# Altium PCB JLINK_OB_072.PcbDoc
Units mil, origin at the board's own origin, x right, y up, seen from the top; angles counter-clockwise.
Board outline 1377.95 x 708.66 mil, 2 copper layers (Top Layer, Bottom Layer); 27 components, 25 nets, 147 pads, 33 vias.
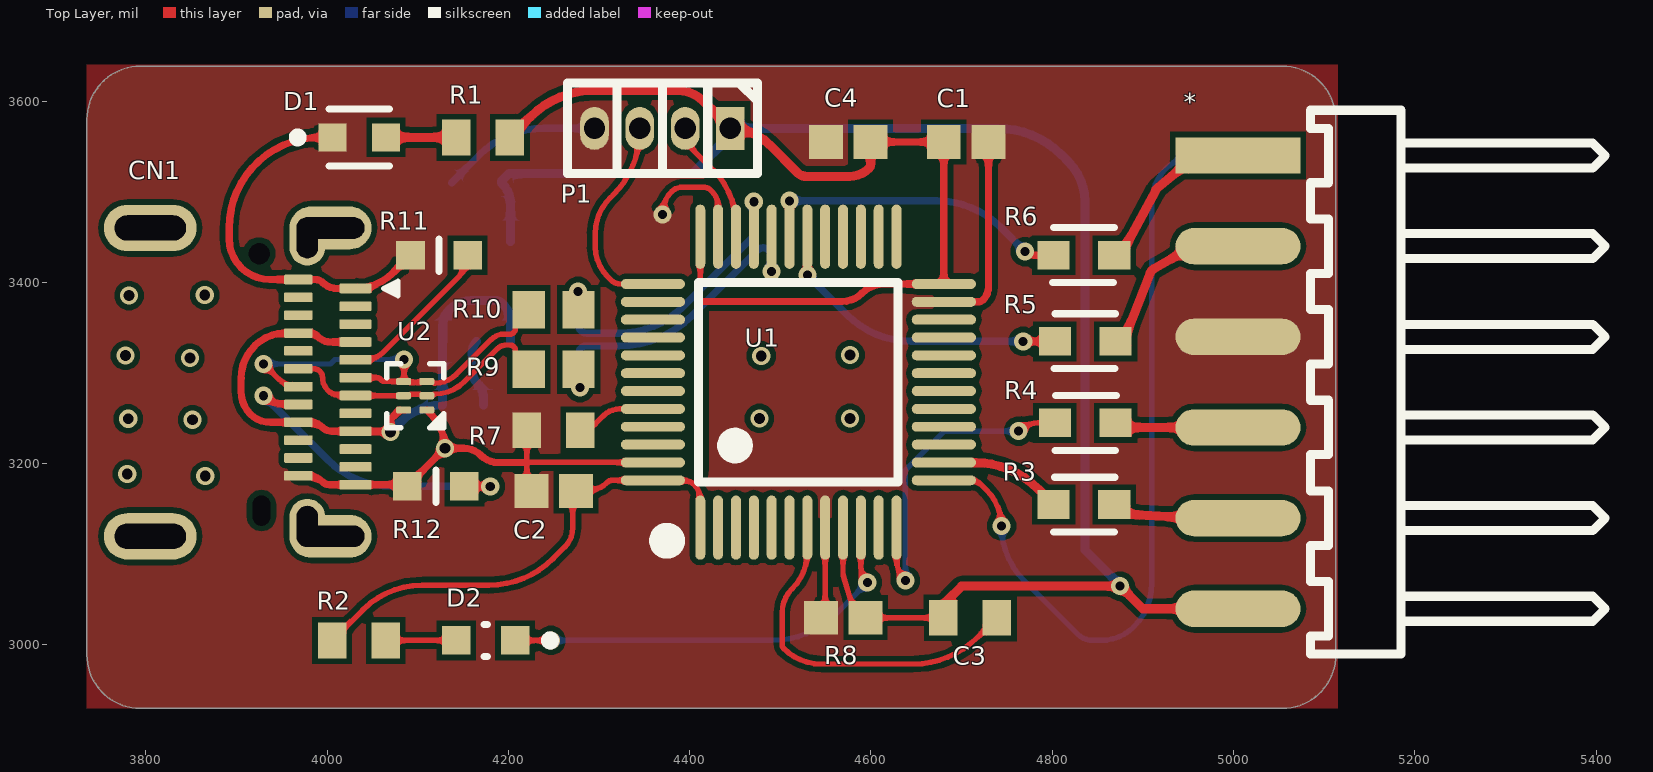
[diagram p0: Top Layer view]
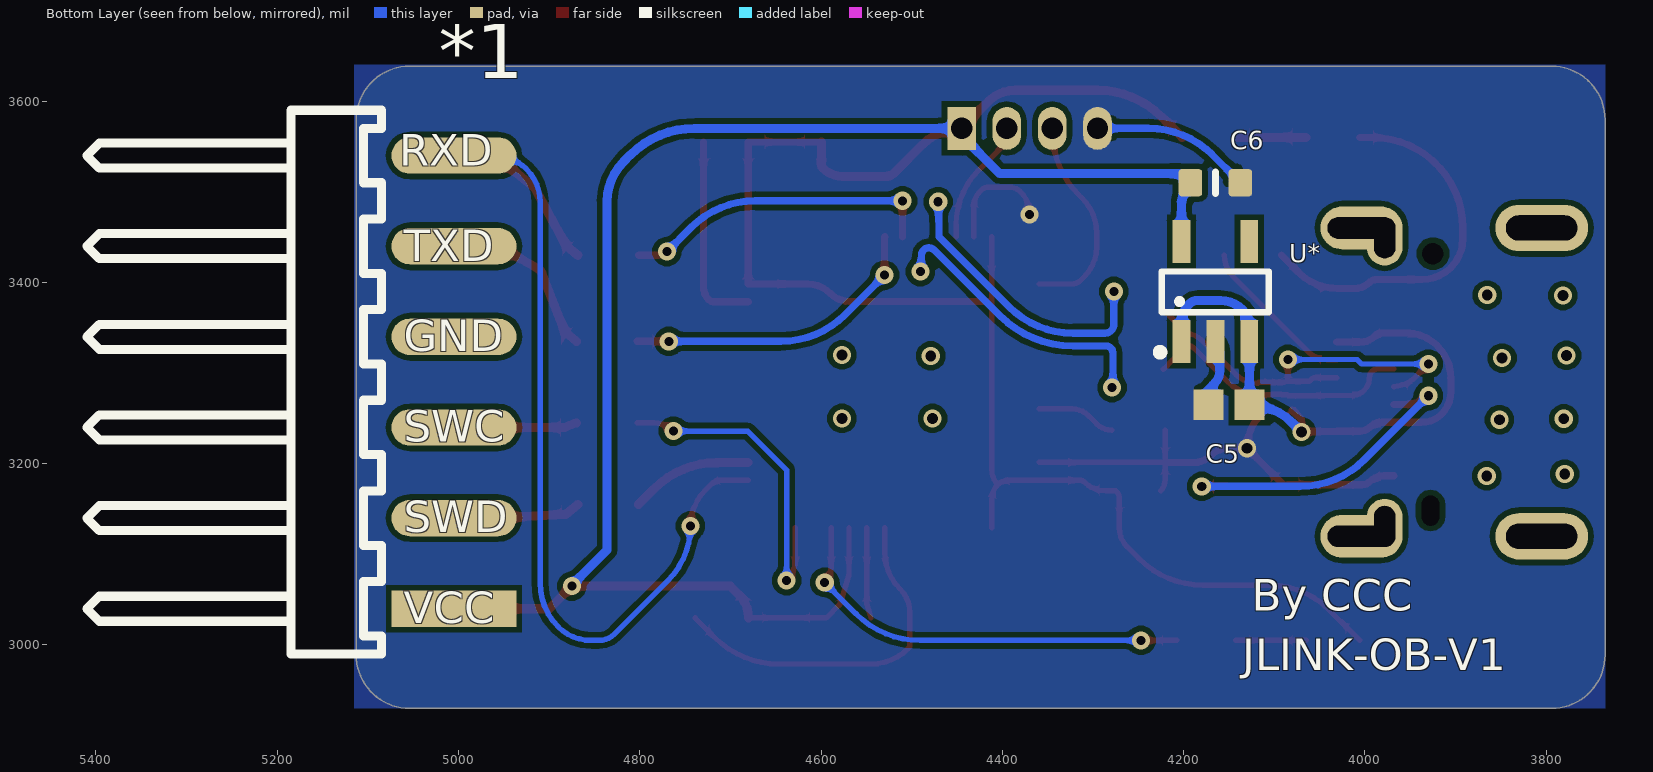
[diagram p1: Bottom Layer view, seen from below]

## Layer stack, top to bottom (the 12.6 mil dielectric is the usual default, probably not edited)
Top Solder: solder mask 0.4, Solder Resist, Dk 3.5
Top Layer: signal copper 1.4
Dielectric 1: dielectric 12.6, FR-4, Dk 4.8
Bottom Layer: signal copper 1.4
Bottom Solder: solder mask 0.4, Solder Resist, Dk 3.5

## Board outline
3735,2989.06 3735,3579.61 cw(c3794.06,3579.61) 3794.06,3638.66 5053.9,3638.66 cw(c5053.9,3579.61) 5112.95,3579.61 5112.95,2989.06 cw(c5053.9,2989.06) 5053.9,2930 3794.06,2930 cw(c3794.06,2989.06)

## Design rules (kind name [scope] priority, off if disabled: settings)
Clearance [All] p1: gap=6 ignorepadtopadclearanceinfootprint=FALSE
DiffPairsRouting DiffPair_DiffPairsRouting [All] p1: maxlimit=8 minlimit=6 mostfreqgap=6 toplayer_minwidth=6 toplayer_maxwidth=8 toplayer_prefwidth=6 bottomlayer_minwidth=6 bottomlayer_maxwidth=8 bottomlayer_prefwidth=6 maxuncoupledlength=500
DiffPairsRouting [All] p2: maxlimit=10 minlimit=10 mostfreqgap=10 toplayer_minwidth=15 toplayer_maxwidth=15 toplayer_prefwidth=15 bottomlayer_minwidth=15 bottomlayer_maxwidth=15 bottomlayer_prefwidth=15 maxuncoupledlength=500
MatchedLengths DiffPair_MatchedLengths [All] p1: tolerance=1000 checknetsindiffpair=FALSE checkdiffpairvsdiffpair=TRUE checkxsignals=TRUE checkothers=TRUE
PolygonConnect [All] p1: connectstyle=Direct reliefconductorwidth=10 reliefentries=4 polygonreliefangle="90 Angle" airgapwidth=10
RoutingVias [All] p1: holewidth=10 width=20 viastyle="Through Hole" minholewidth=10 minwidth=20 maxholewidth=12 maxwidth=24
SolderMaskExpansion [All] p1: expansion=4 istentingtop=FALSE
Width [All] p1: maxlimit=10 minlimit=6 preferedwidth=6
29 further rules are at their usual default settings.

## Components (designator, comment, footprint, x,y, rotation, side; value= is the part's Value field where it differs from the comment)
* "2.54排针6p" HDR2.54-WS-6P 5005,3290 r270 top
*1 "2.54排针6p" HDR2.54-WS-6P 5005,3290 r90 bottom
C1 "Capacitor 100 nF +/-10% 50 V 0603" CAPC1608X90X40NL10T20 4705,3555 r0 top value=100nF
C2 "Capacitor 100 nF +/-10% 50 V 0603" CAPC1608X90X40NL10T20 4250,3170 r180 top value=100nF
C3 "Capacitor 100 nF +/-10% 50 V 0603" CAPC1608X90X40NL10T20 4569.53,3030 r180 top value=100nF
C4 "Capacitor 100 nF +/-10% 50 V 0603" CAPC1608X90X40NL10T20 4575,3555 r180 top value=100nF
C5 "Capacitor 1 uF +/- 10% 25 V 0603" CAPC1608X90X40LL10T20 4150,3265 r180 bottom value=1µF
C6 "Capacitor 4.7µF +/-20% 10V 0603" CAPC0603(1608)100_L 4165,3510 r0 bottom value=4.7µF
CN1 "DX07S024JJ3R1300" JAE-DX07S024JJ3_V 3925,3290 r270 top
D1 "597-3901-831F" FP-597-3901-831F-MFG 4035.5,3560 r0 top
D2 "APT1608ZGCK" FP-APT1608ZGCK-MFG 4175,3005 r180 top
P1 "1.27排针4p" HDR1.27-LI-4P 4370,3570 r180 top
R1 "Resistor 1k +/-1% 0603 100 mW" RESC1608X55X25ML10T15 4172.11,3560 r180 top value=1k
R2 "Resistor 1k +/-1% 0603 100 mW" RESC1608X55X25ML10T15 4035.16,3005 r0 top value=1k
R3 "RC0603JR-07100RL" FP-RC0603-0_55-MFG 4835,3155 r180 top value=100
R4 "RC0603JR-07100RL" FP-RC0603-0_55-MFG 4836.54,3245 r180 top value=100
R5 "RC0603JR-07100RL" FP-RC0603-0_55-MFG 4836.54,3335 r0 top value=100
R6 "RC0603JR-07100RL" FP-RC0603-0_55-MFG 4835,3430 r0 top value=100
R7 "Resistor 10k +/-1% 0603 100 mW" RESC1608X55X25ML10T15 4250,3236.99 r180 top value=10k
R8 "Resistor 10k +/-1% 0603 100 mW" RESC1608X55X25ML10T15 4709.53,3030 r180 top value=10k
R9 "Resistor 22R +/-1% 0603 100 mW" RESC1609X50X30ML08T20 4250,3303.99 r180 top value=22
R10 "Resistor 22R +/-1% 0603 100 mW" RESC1609X50X30ML08T20 4250,3370 r180 top value=22
R11 "RC1608J512CS" FP-RC1608-MFG 4123.5,3430 r0 top value=5.1k
R12 "RC1608J512CS" FP-RC1608-MFG 4120,3175 r180 top value=5.1k
U1 "STM32F072CBT6TR" "LQFP48 7X7_N" 4520,3290 r0 top
U2 "ESDR0502NMUTBG" ONSC-UDFN-6-517AA-01_V 4097.2,3275 r180 top
U* "ME6211C33M5G-N" SOT23-5N 4165,3390 r180 bottom

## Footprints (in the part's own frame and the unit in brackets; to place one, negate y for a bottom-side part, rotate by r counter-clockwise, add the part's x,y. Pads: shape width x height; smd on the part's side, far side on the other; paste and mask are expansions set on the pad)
CAPC0603(1608)100_L [mm] "Chip Capacitor, Body 1.6x0.8mm, Height 1.0mm, IPC High Density"
  rrect25% 0.66x0.76 smd: 1(-0.7,0) 2(0.7,0)
  silkscreen extent 0,-0.3 0,0.3, body extent -0.8,-0.4 0.8,0.4, height 0.95
CAPC1608X90X40LL10T20 [mm] "Chip Capacitor, 2-Leads, Body 1.70x0.90mm, IPC High Density"
  rect 0.85x0.85 smd: 1(-0.575,0) 2(0.575,0)
  body extent -0.85,-0.45 0.85,0.45, height 0.9
CAPC1608X90X40NL10T20 [mm] "Chip Capacitor, 2-Leads, Body 1.70x0.90mm, IPC Medium Density"
  rect 0.95x0.95 smd: 1(-0.625,0) 2(0.625,0)
  body extent -0.85,-0.45 0.85,0.45, height 0.9
FP-597-3901-831F-MFG [mil]
  rect 31x31 smd paste+0 mask+0: 1(-29.5,0) 2(29.5,0)
  silkscreen extent -73,-31 34,31, body extent -49,-22 49,22, height 10
FP-APT1608ZGCK-MFG [mm]
  rect 0.8x0.8 smd paste+0 mask+0: 1(-0.825,0) 2(0.825,0)
  silkscreen extent -1.92,-0.45 0.05,0.45, body extent -1.33,-0.55 1.33,0.55, height 0.25
FP-RC0603-0_55-MFG [mm]
  rect 0.9x0.8 smd paste+0 mask+0: 1(-0.85,0) 2(0.85,0)
  silkscreen extent -0.87,-0.76 0.85,0.77, body extent -1.4,-0.55 1.4,0.55, height 0.25
FP-RC1608-MFG [mm]
  rect 0.8x0.8 smd paste+0 mask+0: 1(-0.8,0) 2(0.8,0)
  silkscreen extent 0,-0.45 0,0.45, body extent -1.3,-0.55 1.3,0.55, height 0.25
HDR1.27-LI-4P [mm] "直插，脚距：1.27mm"
  rect 0.8x1.2 hole 0.6: 1(-1.905,0)
  oval 0.8x1.2 hole 0.6: 2(-0.635,0) 3(0.635,0) 4(1.905,0)
  silkscreen extent -2.67,-1.27 2.67,1.27, body extent -2.54,-1.24 2.54,1.16, height 4.48
HDR2.54-WS-6P [mm] "6P卧式贴片排针2.54"
  rect 1.02x3.5 smd: 1(-6.35,0)
  oval 1.02x3.5 smd: 2(-3.81,0) 3(-1.27,0) 4(1.27,0) 5(3.81,0) 6(6.35,0)
  silkscreen extent -7.62,2.03 7.62,10.29, body extent -7.62,-0.76 7.62,10.34, height 2.54
JAE-DX07S024JJ3_V [mm] "THD, 24-Leads, Body 8.17x8.94mm, Pitch 0.5mm"
  oval 1.2x2.3 hole 0.6 slot 1.9 at 90 deg: 1(-4.32,2) 2(4.32,2)
  oval 1.5x1 hole 0.6 slot 1.1 at 0 deg: 1(-4.02,1.35) 2(4.02,1.35)
  oval 1.3x2.6 hole 0.7 slot 2 at 90 deg: 3(-4.32,-3.05) 4(4.32,-3.05)
  rrect25% 0.27x0.9 smd: A1(-2.625,2.7) A2(-2.125,2.7) A3(-1.625,2.7) A4(-1.125,2.7) A5(-0.625,2.7) A6(-0.125,2.7) A7(0.375,2.7) A8(0.875,2.7) A9(1.375,2.7) A10(1.875,2.7) A11(2.375,2.7) A12(2.875,2.7)
  rrect25% 0.27x0.8 smd: B1(2.625,1.1) B2(2.125,1.1) B3(1.625,1.1) B4(1.125,1.1) B5(0.625,1.1) B6(0.125,1.1) B7(-0.375,1.1) B8(-0.875,1.1) B9(-1.375,1.1) B10(-1.875,1.1) B11(-2.375,1.1) B12(-2.875,1.1)
  round 0 hole 0.6 unplated: H1(-3.6,0)
  round 0 hole 0.5 slot 0.85 at 0 deg unplated: H2(3.6,0.065)
  silkscreen extent -2.83,3.49 -2.43,3.89, body extent -4.47,-5.35 4.47,2.8, height 3.16
"LQFP48 7X7_N" [mm] "48脚，体宽7x7mm，脚距0.5mm"
  oval 0.279x1.8 smd: 1(-2.75,-4.075) 2(-2.25,-4.075) 3(-1.75,-4.075) 4(-1.25,-4.075) 5(-0.75,-4.075) 6(-0.25,-4.075) 7(0.25,-4.075) 8(0.75,-4.075) 9(1.25,-4.075) 10(1.75,-4.075) 11(2.25,-4.075) 12(2.75,-4.075) 25(2.75,4.075) 26(2.25,4.075) 27(1.75,4.075) 28(1.25,4.075) 29(0.75,4.075) 30(0.25,4.075) 31(-0.25,4.075) 32(-0.75,4.075) 33(-1.25,4.075) 34(-1.75,4.075) 35(-2.25,4.075) 36(-2.75,4.075)
  oval 1.8x0.279 smd: 13(4.075,-2.75) 14(4.075,-2.25) 15(4.075,-1.75) 16(4.075,-1.25) 17(4.075,-0.75) 18(4.075,-0.25) 19(4.075,0.25) 20(4.075,0.75) 21(4.075,1.25) 22(4.075,1.75) 23(4.075,2.25) 24(4.075,2.75) 37(-4.075,2.75) 38(-4.075,2.25) 39(-4.075,1.75) 40(-4.075,1.25) 41(-4.075,0.75) 42(-4.075,0.25) 43(-4.075,-0.25) 44(-4.075,-0.75) 45(-4.075,-1.25) 46(-4.075,-1.75) 47(-4.075,-2.25) 48(-4.075,-2.75)
  silkscreen extent -3.93,-4.69 2.79,2.79, body extent -4.5,-4.5 4.5,4.5, height 1.45
ONSC-UDFN-6-517AA-01_V [mm] "SON, 6-Leads, Body 1.2x1mm, Pitch 0.4mm"
  rrect50% 0.42x0.2 smd: 1(-0.325,0.4) 2(-0.325,0) 3(-0.325,-0.4) 4(0.325,-0.4) 5(0.325,0) 6(0.325,0.4)
  silkscreen extent -0.8,-0.9 0.8,0.9, body extent -0.5,-0.6 0.5,0.6, height 0.55
RESC1608X55X25ML10T15 [mm] "Chip Resistor, 2-Leads, Body 1.70x0.90mm, IPC Low Density"
  rect 0.8x1 smd: 1(-0.75,0) 2(0.75,0)
  body extent -0.85,-0.45 0.85,0.45, height 0.55
RESC1609X50X30ML08T20 [mm] "Chip Resistor, 2-Leads, Body 1.65x0.95mm, IPC Low Density"
  rect 0.9x1.05 smd: 1(-0.7,0) 2(0.7,0)
  body extent -0.82,-0.48 0.82,0.48, height 0.5
SOT23-5N [mm] "3x1.6x1.1mm(长宽高)"
  rect 0.5x1.2 smd: 1(-0.95,-1.4) 2(0,-1.4) 3(0.95,-1.4) 4(0.95,1.4) 5(-0.95,1.4)
  silkscreen extent -1.63,-1.78 1.5,0.56, body extent -1.5,-1.4 1.5,1.4, height 1.15

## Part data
* *1: library part CMP-00001-3
C1 C2 C3 C4: library part CMP-001-00017-6, "Chip Capacitor, 100 nF, +/- 10%, 50 V, 0603 (1608 Metric)", Capacitor Type=Ceramic, Case/Package=0603, Max Operating Temperature=125°C, Min Operating Temperature=-55°C, Tolerance=10%, Voltage Rating=50V
C5: library part CMP-001-00005-6, "Chip Capacitor, 1 uF, +/- 10%, 25 V, 0603 (1608 Metric)", Capacitor Type=Ceramic, Case/Package=0603, Max Operating Temperature=125°C, Min Operating Temperature=-55°C, Tolerance=10%, Voltage Rating=25V
C6: library part CMP-001-00076-4, "Chip Capacitor, 4.7µF +/-20%, 10V, 0603, Thickness 1 mm", Case/Package=0603, Max Operating Temperature=85°C, Min Operating Temperature=-55°C, Tolerance=10%, Voltage Rating=10V
CN1: library part CMP-002-00065-4, "USB-C Connector, 20 V, 1.25 A, -30 to 80 degC, RoHS, Tape and Reel"
D1: library part CMP-00000-1, "Smd 0603 White 20Pc Smpl Strip / Dialight Corporation Rohs Compliant: Yes", Case Code (Imperial)=0603, Case Code (Metric)=1608, Color=White, Forward Current=20mA, Forward Voltage=3.4V, Lens Color=Yellow, Max Operating Temperature=80°C, Min Operating Temperature=-20°C, Package Quantity=20, Power Rating=70mW, Test Current=10mA
D2: library part CMP-007-00036-1, "LED Uni-Color Green 515nm 2-Pin Chip LED T/R", Case/Package=0603, Forward Current=20mA, Forward Voltage=3.3V, Max Operating Temperature=85°C, Min Operating Temperature=-40°C
P1: library part CMP-002-00077-1
R1 R2: library part CMP-009-00014-5, "Chip Resistor, 1 KOhm, +/-1%, 0.1 W, -55 to 155 degC, 0603 (1608 Metric)", Case/Package=0603, Max Operating Temperature=155°C, Min Operating Temperature=-55°C, Power=100mW, Tolerance=1%, Voltage Rating=50V
R3 R4 R5 R6: library part CMP-009-00182-1, "Res Thick Film 0603 100 Ohm 5% 1/10W ±100ppm/°C Molded SMD SMD Paper T/R", Case/Package=0603, Max Operating Temperature=155°C, Min Operating Temperature=-55°C, Tolerance=5%, Voltage Rating=50V
R7 R8: library part CMP-009-00017-5, "Chip Resistor, 10 KOhm, +/- 1%, 01 W, -55 to 155 degC, 0603 (1608 Metric)", Case/Package=0603, Max Operating Temperature=155°C, Min Operating Temperature=-55°C, Power=100mW, Tolerance=1%, Voltage Rating=50V
R9 R10: library part CMP-009-00027-5, "Chip Resistor, 22 Ohm, +/- 1%, 100 mW, -55 to 155 degC, 0603 (1608 Metric)", Case/Package=0603, Max Operating Temperature=155°C, Min Operating Temperature=-55°C, Power=100mW, Tolerance=1%, Voltage Rating=75V
R11 R12: library part CMP-009-00183-1, "Res Thick Film 0603 5.1K Ohm 5% 1/10W ±100ppm/°C Molded SMD SMD T/R", Case/Package=0603, Max Operating Temperature=155°C, Min Operating Temperature=-55°C, Tolerance=5%
U1: library part CMP-020-00024-2, "MCU 32-Bit GP STM32F 32MHz ARM Cortex M0+ RISC 128kB Flash 48-Pin LQFP T/R", Case/Package=LQFP, Clock Frequency=48MHz, Max Operating Temperature=85°C, Max Supply Voltage=3.6V, Min Operating Temperature=-40°C, Min Supply Voltage=2V
U2: library part CMP-004-00025-1, "Ultra Low Capacitance ESD Protection Array for High Speed Data Line Protection, 6-Pin UDFN, Pb-Free, Tape and Reel"
U*: library part CMP-019-00052-1, "VIN=6.5V Vo=3.3V Io=600mA"

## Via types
v1: diameter 20, hole 10, Top Layer to Bottom Layer, 19 vias
v2: diameter 20, hole 12, Top Layer to Bottom Layer, 14 vias

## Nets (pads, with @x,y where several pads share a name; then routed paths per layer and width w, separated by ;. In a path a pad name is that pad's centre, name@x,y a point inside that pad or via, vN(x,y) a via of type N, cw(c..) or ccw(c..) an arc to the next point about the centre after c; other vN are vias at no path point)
+5: C5.2 CN1.A4 CN1.A9 CN1.B4 CN1.B9 U2.6 U*.1 U*.3 | length 668.5
  Top Layer w8: CN1.A4 4003.78,3334.29 cw(c4003.78,3353.78) 3990,3340 ccw(c3980.02,3330.02) 3980.02,3344.13 CN1.B9 3954.12,3344.13 ccw(c3954.12,3295.88) 3920,3330 ccw(c3955.84,3294.15) 3905.15,3294.15 3905,3279.99 ccw(c3941.2,3279.99) 3915.29,3254.71 ccw(c3937.43,3277.43) 3937.43,3245.71 CN1.B4 3981.22,3245.71 cw(c3981.22,3226.22) 3995,3240 ccw(c4004.98,3249.98) 4004.98,3235.87 CN1.A9 4031.73,3235.43 4069.57,3235.43 v2(4070,3235) 4070.21,3235.21 4070.21,3249.26 U2.6@4080.14,3259.19
  Bottom Layer w10: v2(4070,3235) 4080.65,3245.65 cw(c4127.36,3198.94) C5.2 4127.36,3334.65 U*.3 4127.6,3352.13 cw(c4152.87,3352.13) 4135,3370 cw(c4159.14,3345.86) 4159.14,3380 4185,3380 cw(c4185,3367.93) 4193.54,3376.46 4195,3375 cw(c4177.13,3357.13) 4202.4,3357.13 U*.1
boot: R7.1 U1.44 | length 87.7
  Top Layer w6: R7.1 ccw(c4279.53,3259.85) 4295.69,3243.69 4305,3253 cw(c4323.04,3234.96) 4323.04,3260.47 U1.44
GND: *.3 C1.2 C2.2 C3.2 C4.2 C5.1 C6.1 CN1.A1 CN1.A12 CN1.B1 CN1.B12 D1.1 P1.4 R7.2 R11.1 R12.2 U1.8 U1.23 U1.35 U1.47 U2.1 U*.2 | length 1655.1
  Top Layer w6: 4220.47,3201.42 R7.2 ; C2.2 cw(c4237.27,3181.88) 4220.47,3181.88 4220.47,3200 cw(c4223.89,3196.58) 4223.89,3201.42 U1.47 ; v1(4370,3475) 4370,3475.86 cw(c4404.14,3475.86) 4380,3500 cw(c4392.07,3487.93) 4392.07,3505 4415,3505 cw(c4415,3492.93) 4423.54,3501.46 4425,3500 cw(c4409.51,3484.51) 4431.42,3484.51 U1.35 ; C3.2 4549.53,3045.7 U1.8
  Top Layer w8: CN1.B1 3978.94,3186.65 cw(c3978.94,3163.94) 3995,3180 ccw(c4002.7,3187.7) 4002.7,3176.81 CN1.A12 4084.13,3176.81 cw(c4084.13,3170.63) R12.2 4088.5,3175.5 v2(4130,3217) ; D1.1 3992,3560 ccw(c3992,3460) 3892,3460 3892,3448 ccw(c3936.81,3448) 3936.81,3403.19 CN1.B12 3987.3,3403.19 cw(c3987.3,3392.3) 3995,3400 ccw(c4011.06,3416.06) 4011.06,3393.35 CN1.A1 ccw(c4031.3,3451.42) 4072.36,3410.36 R11.1 ; U2.1 4114.27,3254.99 cw(c4076.28,3217) v2(4130,3217) ; 4220.47,3201.42 4188.31,3201.42 cw(c4188.31,3227.31) 4170,3209 ccw(c4150.69,3189.69) 4150.69,3217 v2(4130,3217) ; U1.23 4718.16,3378.58 ccw(c4718.16,3386.84) 4724,3381 ccw(c4710.47,3394.53) 4729.61,3394.53 C1.2
  Bottom Layer w8: C6.1 4168.15,3540.71 cw(c4238.86,3470) 4238.86,3570 P1.4
  Bottom Layer w10: U*.2 ccw(c4177.07,3322.81) 4160,3322.81 4160,3302.07 ccw(c4177.07,3302.07) 4165,3290 cw(c4146.56,3271.56) 4172.64,3271.56 C5.1
NetCN1_A5: CN1.A5 R11.2 | length 177
  Top Layer w6: CN1.A5 4041.74,3314.61 ccw(c4041.74,3343.26) 4062,3323 4145.1,3406.1 ccw(c4121.2,3430) R11.2
NetCN1_B5: CN1.B5 R12.1 | length 356.5
  Top Layer w8: v1(3930,3275) ccw(c3953.19,3298.19) 3953.19,3265.39 CN1.B5 ; R12.1 v1(4180,3175)
  Bottom Layer w8: v1(3930,3275) 4000.71,3204.29 ccw(c4071.42,3275) 4071.42,3175 v1(4180,3175)
NetD1_2: D1.2 R1.2 | length 77.6
  Top Layer w10: D1.2 R1.2
NetD2_1: D2.1 U1.10 | length 473.2
  Top Layer w6: D2.1 v1(4247,3005) ; U1.10 4588.9,3086.15 ccw(c4613.15,3086.15) v1(4596,3069)
  Bottom Layer w6: v1(4247,3005) 4490.58,3005 ccw(c4490.58,3105) 4561.29,3034.29 v1(4596,3069)
NetD2_2: D2.2 R2.2 | length 77.8
  Top Layer w6: R2.2 D2.2
NetR3_2: R3.2 U1.14 | length 136
  Top Layer w10: U1.14 4713.7,3201.42 cw(c4713.7,3101.42) 4784.41,3172.13 R3.2
NetR4_2: R4.2 U1.12 | length 368.4
  Top Layer w6: U1.12 4628.27,3094.5 ccw(c4661.5,3094.5) v1(4638,3071) ; v1(4763,3236) cw(c4784.73,3214.27) 4784.73,3245 R4.2
  Bottom Layer w6: v1(4638,3071) 4638,3193 4681,3236 v1(4763,3236)
NetR5_1: R5.1 U1.30 | length 341.5
  Top Layer w8: U1.30 4530,3450.29 v1(4530,3408) ; v1(4768,3335) R5.1
  Bottom Layer w8: v1(4530,3408) 4573.71,3364.29 ccw(c4644.42,3435) 4644.42,3335 v1(4768,3335)
NetR6_1: R6.1 U1.31 | length 351
  Top Layer w8: U1.31 v1@4510.16,3490.05 ; v1(4770,3434) ccw(c4779.66,3443.66) 4779.66,3430 R6.1
  Bottom Layer w8: v1(4510.14,3490.06) 4672.52,3490.06 cw(c4672.52,3390.06) 4743.23,3460.77 v1(4770,3434)
rst: R8.1 U1.7 | length 397.9
  Top Layer w6: U1.7 4529.84,3102.66 cw(c4472.34,3102.66) 4513,3062 ccw(c4539.56,3035.44) 4502,3035.44 4502,3000.83 ccw(c4508.83,3000.83) 4504,2996 ccw(c4545.04,3037.04) 4545.04,2979 4646.63,2979 ccw(c4646.63,3079) 4717.34,3008.29 R8.1
RXD: *.1 R6.2 | length 187.3
  Top Layer w10: R6.2 4881.18,3440.75 4914.26,3501.79 cw(c4923.05,3497.03) 4916.68,3504.74 4941.1,3524.92 *.1
SWC: *.4 R4.1 | length 135.9
  Top Layer w10: R4.1 4882.72,3240 *.4
swclk: P1.3 U1.37 | length 233.7
  Top Layer w6: P1.3 4345,3567.42 cw(c4245,3567.42) 4315.71,3496.71 4312,3493 ccw(c4350.63,3454.37) 4296,3454.37 4296,3439 ccw(c4341.87,3439) 4309.44,3406.56 4314,3402 ccw(c4323.01,3411.01) 4323.01,3398.27 U1.37
SWD: *.5 R3.1 | length 140.6
  Top Layer w10: R3.1 4881.18,3144.25 4956.18,3140 *.5
swio: P1.2 U1.34 | length 137.5
  Top Layer w6: P1.2 ccw(c4431.21,3570) 4405.61,3544.39 4426,3524 cw(c4365.4,3463.4) 4451.1,3463.4 U1.34
SWO: *1.6 U1.13 | length 911.6
  Top Layer w6: U1.13 4710.38,3181.73 cw(c4710.38,3166.41) 4721.21,3177.25 4727.83,3170.63 cw(c4688.63,3131.44) v1(4744.06,3131.44)
  Bottom Layer w6: v1(4744.06,3131.44) ccw(c4829.77,3131.44) 4769.16,3070.84 4827.93,3012.07 ccw(c4845,3029.14) 4845,3005 4853.79,3005 ccw(c4853.79,3056.21) 4890,3020 ccw(c4841.72,3068.28) 4910,3068.28 4910,3488.79 cw(c4961.21,3488.79) 4925,3525 cw(c4961.21,3488.79) 4961.21,3540 *1.6
TXD: *.2 R5.2 | length 191.8
  Top Layer w10: R5.2 4882.72,3345.75 4908.14,3410.28 cw(c4917.45,3406.62) 4912.53,3415.32 4956.18,3440 *.2
USB-DM: R9.1 U1.32 | length 316.4
  Bottom Layer w8: v1(4279,3284) cw(c4281.41,3286.41) 4278,3286.41 4278,3322 cw(c4286,3322) 4280.34,3327.66 cw(c4286,3322) 4286,3330 4322.15,3330 ccw(c4322.15,3443.79) 4402.61,3363.33 4474.6,3435.32 ; 4474.61,3435.33 cw(c4481.85,3428.08) 4478.57,3437.78 cw(c4481.12,3430.2) 4489.1,3430.78 v1(4490.47,3411.87)
USB-DP: R10.1 U1.33 | length 313.2
  Bottom Layer w8: v1(4277,3390) 4277,3353.71 ccw(c4286.71,3353.71) 4279.84,3346.84 ccw(c4286.71,3353.71) 4286.71,3344 4322.06,3344 ccw(c4322.06,3444) 4392.77,3373.29 4470,3450.51 4470,3459 v1(4470.79,3489.03)
USBD+: CN1.A6 CN1.B6 R10.2 U2.3 U2.4 | length 457.7
  Top Layer w6: v1(3930,3310) 3945.46,3294.54 ccw(c3968.31,3317.4) 3946.28,3293.75 3946.6,3293.46 cw(c3942.53,3289.04) 3946.67,3293.39 ; 3946.68,3293.38 ccw(c3953.89,3300.78) 3947.59,3292.59 cw(c3943.87,3287.88) 3947.68,3292.52 ccw(c3968.31,3317.4) 3956.18,3287.44 cw(c3953.9,3281.89) 3956.27,3287.4 CN1.B6 ; CN1.A6 4055.08,3294.92 cw(c4064.66,3304.66) 4055,3295 cw(c4055,3290.17) 4058.41,3293.59 4059,3293 ccw(c4064.44,3298.44) 4064.44,3290.75 U2.4 ; v1(4085,3315) 4085,3290.75 U2.4 ; R10.2 4212.17,3359.73 ccw(c4222.91,3348.99) 4207.72,3348.99 cw(c4201.72,3348.99) 4205.97,3344.75 cw(c4201.72,3348.99) 4201.72,3342.99 4195.58,3342.99 ccw(c4195.58,3322.16) 4180.85,3336.89 4142.79,3298.84 cw(c4118.74,3322.89) 4118.74,3288.87 cw(c4118.74,3290.47) 4117.61,3289.34 ccw(c4116.48,3288.21) 4116.48,3289.81 4112.26,3289.81 cw(c4112.26,3293.01) U2.3 cw(c4107.74,3293.01) 4107.74,3289.81 4089.68,3289.81 U2.4
  Bottom Layer w6: v1(3930,3310) 4003.66,3310 4008.66,3315 v1(4085,3315)
USBD-: CN1.A7 CN1.B7 R9.2 U2.2 U2.5 | length 307.6
  Top Layer w6: CN1.B7 3985.24,3304.76 cw(c3985.24,3295) 3995,3295 ccw(c4014.76,3295) 4014.76,3275.24 CN1.A7 4045,3275.24 4045.24,3275 U2.5 cw(c4086.67,3272.74) 4086.67,3275.94 4090.89,3275.94 ccw(c4090.89,3277.54) 4092.02,3276.41 cw(c4093.15,3275.27) 4093.15,3276.87 4101.26,3276.87 cw(c4101.26,3275.27) 4102.39,3276.41 ccw(c4103.52,3277.54) 4103.52,3275.94 4107.74,3275.94 cw(c4107.74,3272.74) U2.2 cw(c4112.26,3272.74) 4112.26,3275.94 4116.48,3275.94 ccw(c4116.48,3277.54) 4117.61,3276.41 cw(c4118.74,3275.27) 4118.74,3276.87 ; 4118.78,3276.87 ccw(c4118.78,3322.79) 4151.25,3290.32 4187.58,3326.65 cw(c4198.07,3316.16) 4198.07,3330.99 4201.72,3330.99 cw(c4201.72,3324.99) 4205.97,3329.24 cw(c4201.72,3324.99) 4207.72,3324.99 ccw(c4222.91,3324.99) 4212.16,3314.27 R9.2
VCC: *.6 C1.1 C2.1 C3.1 C4.1 C6.2 P1.1 R1.1 R2.1 R8.2 U1.1 U1.9 U1.24 U1.36 U1.48 U*.5 | length 3579.1
  Top Layer w6: R2.1 4039.51,3038.87 cw(c4105,2973.38) 4105,3066 4178.58,3066 ccw(c4178.58,3166) 4249.29,3095.29 4262.51,3108.51 ccw(c4242.03,3129) 4271,3129 4271,3161.29 cw(c4283.31,3161.29) C2.1 4285.86,3170 ccw(c4285.86,3204.14) 4310,3180 cw(c4314.18,3175.82) 4314.18,3181.73 U1.48 4393.58,3181.73 cw(c4393.58,3165.58) 4405,3177 ; U1.1 4411.73,3160.75 ccw(c4388.75,3160.75) 4405,3177 ; U1.36 4411.73,3193.25 cw(c4388.75,3193.25) 4405,3177 ; U1.9 4569.21,3078.6 ccw(c4575.21,3078.6) 4569.47,3076.86 4578.69,3046.45 ccw(c4584.43,3048.19) 4580.19,3043.95 C3.1 R8.2
  Top Layer w8: 4413,3379 4568.27,3379 ccw(c4568.27,3409.73) 4590,3388 cw(c4614.79,3363.21) 4614.79,3398.27 U1.24 U1.24 C1.1 C4.1
  Top Layer w10: R1.1 4224.35,3582.71 cw(c4295.06,3512) 4295.06,3612 4386,3612 cw(c4386,3570.96) 4415.02,3599.98 ; 4416.02,3598.98 P1.1 ; P1.1@4446,3569 P1.1 ; C4.1 4599.61,3529.88 cw(c4594.12,3529.88) 4598,3526 cw(c4576.27,3547.73) 4576.27,3517 4528.66,3517 cw(c4528.66,3530.66) 4519,3521 4487.68,3552.32 ccw(c4445,3509.64) P1.1 ; R8.2 cw(c4716.21,3030) 4690.61,3055.61 4700,3065 v1(4875,3065) 4900,3040 *.6
  Bottom Layer w10: U*.5 4202.4,3486.24 ccw(c4168.8,3486.24) C6.2 4192.56,3511.96 4200.56,3519.96 4202.52,3519.96 4202.56,3520 4402.87,3520 4445,3562.13 P1.1 4739.58,3570 cw(c4739.58,3470) 4810.29,3540.71 4818,3533 cw(c4774.54,3489.54) 4836,3489.54 4836,3146.42 4836,3105 4875,3066 v1(4875,3065)
pads on no net: *1.1 *1.2 *1.3 *1.4 *1.5 CN1.1 CN1.2 CN1.3 CN1.4 CN1.A2 CN1.A3 CN1.A8 CN1.A10 CN1.A11 CN1.B2 CN1.B3 CN1.B8 CN1.B10 CN1.B11 CN1.H1 CN1.H2 U1.2 U1.3 U1.4 U1.5 U1.6 U1.11 U1.15 U1.16 U1.17 U1.18 U1.19 U1.20 U1.21 U1.22 U1.25 U1.26 U1.27 U1.28 U1.29 U1.38 U1.39 U1.40 U1.41 U1.42 U1.43 U1.45 U1.46 U*.4
copper on no net:
  other v2: 3865.57,3186.54 3779.57,3188.54 3851.57,3248.54 3780.57,3249.54 4477,3250 4577,3250 3848.57,3316.54 4479,3319 3777.57,3319.54 4577,3320 3781.57,3385.54 3865,3386

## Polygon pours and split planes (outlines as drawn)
GND on Bottom Layer "GND_L02_P000" (solid, pour order 0): 3735,3640 5115,3640 5115,2930 3735,2930
GND on Top Layer "GND_L01_P001" (solid, remove dead copper, pour order 1): 3735,3640 5115,3640 5115,2930 3735,2930

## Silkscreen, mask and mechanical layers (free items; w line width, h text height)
Bottom Overlay:
  text "RXD" at 5065.25,3516.95 h60
  text "TXD" at 5060.25,3411.95 h60
  text "GND" at 5060.25,3312.61 h60
  text "SWC" at 5060.25,3212.61 h60
  text "SWD" at 5060.25,3112.61 h60
  text "By CCC" at 4125,3026.27 h60
  text "VCC" at 5060.19,3012.61 h60
  text "JLINK-OB-V1" at 4135.11,2960.67 h60
Mechanical 5:
  the board outline again, w3.94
